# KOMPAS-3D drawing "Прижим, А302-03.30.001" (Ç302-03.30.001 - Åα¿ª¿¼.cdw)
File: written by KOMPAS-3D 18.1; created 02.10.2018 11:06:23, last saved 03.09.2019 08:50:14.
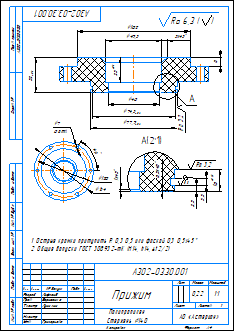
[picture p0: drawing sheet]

Sheet 1: A4, portrait

Document properties: Автор: Милов; Масса: 0.218817; Параметр неуказанной шероховатости: Ra 6,3; Полное имя файла: ..\3Д ПВХ\А302-01.30.001 - Прижим.m3d

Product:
- Part/product: Прижим  | designation А302-03.30.001
    Масса: 0.218817
    Раздел спецификации: Детали
    Форматы листов документа: A4
- Part/product: Прижим  | designation А302-01.30.001
    Масса: 0.21871
    Раздел спецификации: Детали
    Форматы листов документа: A4
    source file: ..\3Д ПВХ\А302-01.30.001 - Прижим.cdw
  - Component: Прижим  | designation А302-01.30.001  | Масса: 0.22; Раздел спецификации: Детали; Форматы листов документа: A4; source file: ..\3Д ПВХ\А302-01.30.001 - Прижим.cdw

Title block, sheet 1: Наименование: Прижим; designation: А302-03.30.001; Масса: 0,22; scale: 1:1; Количество листов документа: 1; organisation: АО «Астерион»; Форматы листов документа: A4; stored path: \\192.168.87.28\Konstructor_doc\Мембранные насосы\Мембранный электропривод\А302-00.00.000 - ASTRA-302 (МЭ200)\3Д ПВХ\А302-01.30.001 - Прижим.cdw; Разработал: Лифлянд; Проверил: Борисенко; Т. контр.: Лучихин; Утвердил: Григорьева

Views: Вид 1, Местный разрез 1, Вид:1, Проекционный вид 2, Выносной элемент 3, Проекционный вид 4, Выносной элемент А, Выносной элемент
Referenced files in D:\Мембранные насосы\Мембранный электропривод\А302-00.00.000 - ASTRA-302 (МЭ200)\3Д ПВХ\: А302-01.30.001 - Прижим.m3d
Referenced files in \\192.168.87.28\Konstructor_doc\Мембранные насосы\Мембранный электропривод\А302-00.00.000 - ASTRA-302 (МЭ200)\3Д ПВХ\: А302-01.30.001 - Прижим.m3d
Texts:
  Полипропилен
  Стержень  140
  Ra 3,2
  Ra 6,3
  Ra 6,3 ( )
Dimensions and other numbers on the sheet: 46; 49,5; 8; 32; 102; 74,3; 77,9; 5; 23; 4; 1; 0,5; 2,5; 3,3; 10; 0,8; 134; 120; 7; 6 отв.; 1:1; 0,22

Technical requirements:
  Острые кромки притупить R 0,3...0,5 или фаской 0,3...0,5х45 .
  Общие допуски ГОСТ 30893.2-mK (H14, h14,  t2/2).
